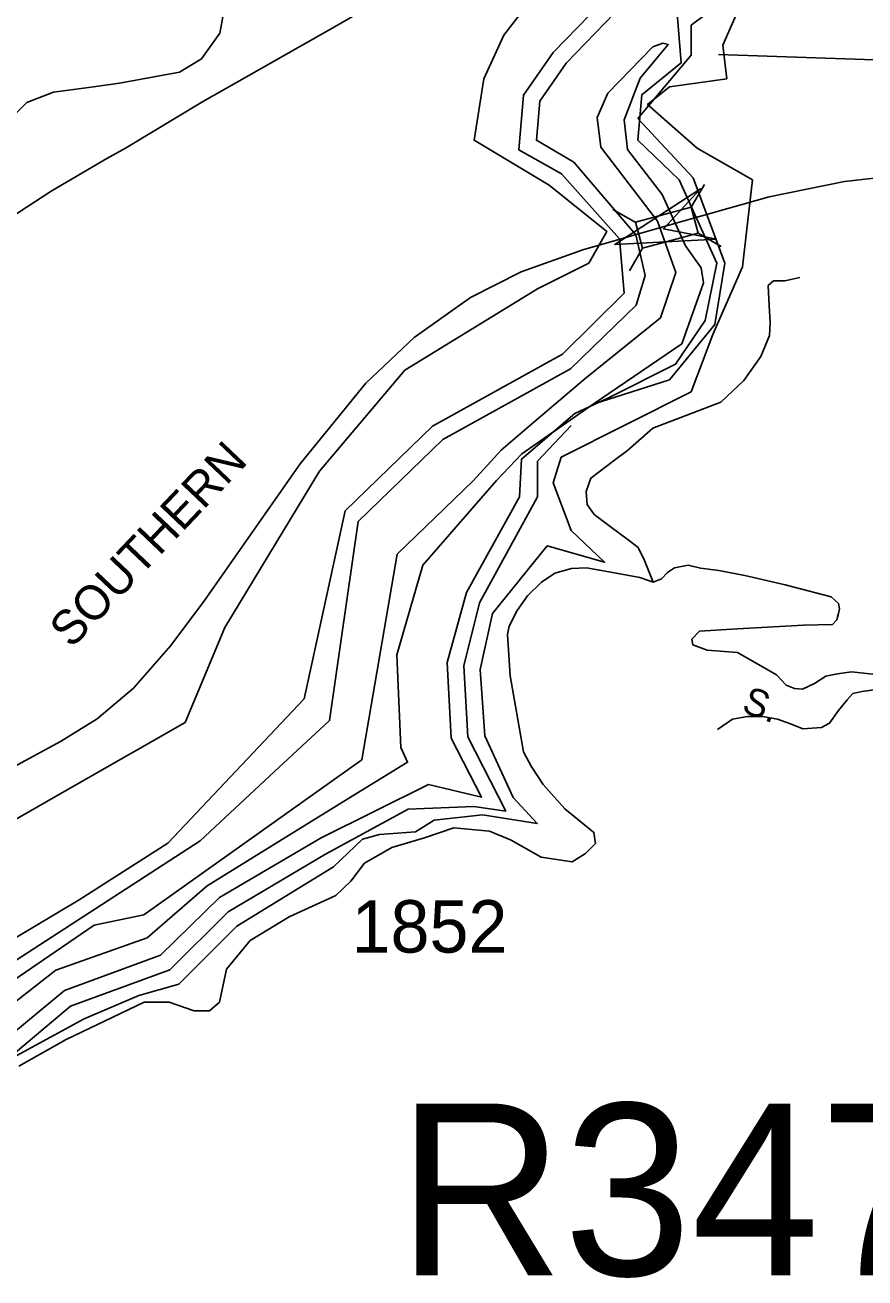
# Model space of a CAD drawing. Extents: x 884530 to 1028605, y 526725 to 653634.
# Drawn here: x 983469 to 985472, y 554302 to 557289 of the extents above; entities that cross this region are included whole.
import ezdxf

# ---------------------------------------------------------------- set-up
doc = ezdxf.new("R2010")
doc.units = 0
for name, color, linetype in [('Exist Hydrographic Bay Label', 7, 'Continuous'), ('Exist Hydrographic Buffer Line', 7, 'Continuous'), ('Exist Hydrographic Creek Single Shore', 7, 'Continuous'), ('Exist Railroad Mainline', 7, 'Continuous'), ('Exist Railroad Mainline Label', 7, 'Continuous'), ('Exist Road Non-System Type 51', 7, 'Continuous'), ('Exist Road Primary Interstate Structure Standard Bridge CELL', 7, 'Continuous'), ('Exist Road Primary US Structure RailRoad Number Label', 7, 'Continuous'), ('Exist Road Secondary Structure Standard Bridge Attributed CELL', 7, 'Continuous'), ('Exist Road Secondary Type 41 Attributed', 7, 'Continuous'), ('Exist Road Secondary Type 51 Attributed', 7, 'Continuous'), ('Exist Road Secondary Type 51 Label', 7, 'Continuous'), ('Exist Road Secondary Type 51 Number Label', 7, 'Continuous'), ('Exist Utilities Electrical Transmission Line', 7, 'Continuous')]:
    doc.layers.add(name, color=color, linetype=linetype)

msp = doc.modelspace()

# ---------------------------------------------------------------- linework, layer by layer
at = {"layer": 'Exist Hydrographic Bay Label'}
for points in [[(981773.4, 554673.1), (981811.5, 554652.9), (981929.6, 554719), (982322.3, 554872), (982708.3, 555125.6), (983123.8, 555210.7), (983586.4, 555475.2), (983850.8, 555626.4), (983945.2, 555853.1), (984171.7, 556225.9), (984374.7, 556466.8), (984691, 556660.5), (984813.8, 556721.9), (984856.3, 556797.5), (984719.3, 556907.6), (984539.9, 557014.8), (984563.5, 557161.2), (984610.8, 557265.2), (984738.2, 557430.5)], [(985185.3, 557359.6), (985133.4, 557241.5)], [(983449.1, 554832), (983610.4, 554920), (983740.7, 554975.4), (983836.2, 555002.3), (983974.4, 555140.6), (984205.1, 555282.6), (984273.5, 555347.8), (984314.2, 555359.2), (984400.6, 555365.7), (984444.6, 555393.4), (984560.3, 555406.5), (984690.6, 555385.3), (984633.6, 555447.2), (984565.4, 555594.7), (984554.3, 555752.5), (984583.8, 555886.4), (984714.6, 556047.9), (984851.5, 556008.6), (984771.3, 556084.2), (984728.8, 556197.6), (984747.7, 556259), (985057.9, 556414.9), (985109.8, 556551.9), (985180.6, 556712.5), (985204.2, 556920.3), (985072, 556995.9), (984954, 557099.8), (985005.9, 557142.3), (985142.8, 557161.2), (985133.4, 557241.5)]]:
    msp.add_lwpolyline(points, dxfattribs=at)
at = {"layer": 'Exist Hydrographic Buffer Line'}
for points in [[(981744.2, 554760.7), (981742.3, 554662.6), (981809, 554593.9), (981858, 554593.9), (981971.8, 554610.2), (982338.1, 554834.7), (982975.8, 554933.8), (983163, 554944.8), (983597.9, 555203.8), (983809.8, 555338.8), (984134.6, 555683.1), (984232.4, 556131), (984441.1, 556333.2), (984750.9, 556504.8), (984898, 556649.9), (984886.9, 556779.6), (984748.5, 556935), (984646.8, 556991.8), (984657.8, 557122), (984728.8, 557223.9), (984875.8, 557376), (984982.3, 557415.1), (985163.7, 557368.8), (985057.9, 557288.8)], [(981686.4, 554786.2), (981692.2, 554652.8), (981714.8, 554627.3), (981793.3, 554552.7), (981987.5, 554562.5), (982353.9, 554797.5), (983154.7, 554889.7), (983372.1, 555011), (983886.9, 555344.3), (984052, 555498.6), (984195.2, 555630.8), (984263.3, 556105.3), (984465.2, 556300.8), (984770.3, 556469.8), (984926.3, 556621.6), (984948.4, 556692), (984925.9, 556788.8), (984777.6, 556962.4), (984688.8, 557014.7), (984696.8, 557108), (984759.8, 557198.3), (984898.3, 557341.6), (984984.5, 557373.3), (985024.8, 557317.1)], [(985024.8, 557317.1), (985034.2, 557199), (984939.8, 557123.4), (984930.4, 557014.8), (985029.5, 556920.3), (985119.2, 556721.9), (985090.9, 556584.9), (985020.1, 556481), (984861, 556400.7), (984780.7, 556362.9), (984653.2, 556254.3), (984648.5, 556164.5), (984521.7, 555936.7), (984476.2, 555769.7), (984485.6, 555589.1), (984558.1, 555448.7), (984431.6, 555478.2), (984175.2, 555351.3), (983933.1, 555209.1), (983792, 555071.3), (983563.5, 554987.1), (983343.9, 554805.8)], [(985057.9, 557288.8), (985057.9, 557217.9), (984930.4, 557066.8)], [(984984.7, 556591.5), (985021.1, 556699.2), (984977.4, 556821.4), (984842.4, 556998.4), (984833.3, 557068.7), (984859.1, 557126.9), (984966, 557237.6), (984990.1, 557246.4), (985003.1, 557242.9), (984936.4, 557163.1), (984898.3, 557063.7), (984906.3, 556992.9), (984988.3, 556885.3), (985044, 556762.9), (985081.9, 556710.5), (985087, 556674.8), (985035.7, 556529.5)], [(984930.4, 557066.8), (985062.6, 556925), (985138.1, 556721.9), (985114.5, 556575.5), (985005.9, 556443.2), (984824.2, 556385.4)], [(984984.7, 556591.5), (984803.8, 556445.7), (984682.6, 556342.9), (984604.4, 556275.9)], [(984653.7, 556266.8), (984824.2, 556385.4), (985035.7, 556529.5)], [(984771.3, 556334.6), (984691, 556249.5), (984691, 556164.5), (984552.8, 555911.6), (984515.2, 555761.1), (984525.5, 555591.9), (984615.5, 555415.3), (984539.1, 555426), (984382.7, 555419.5), (984185.4, 555312.6), (983953.8, 555174.8), (983814.2, 555036.8), (983577.3, 554949.6), (983364.5, 554770.8), (983234, 554765.2), (983157.5, 554734.2), (983004.3, 554589.2), (982937.5, 554639.3)], [(984653.7, 556266.8), (984593.2, 556203.7), (984417.8, 556001.7), (984355.6, 555788.1), (984365.4, 555567), (984381.6, 555531.6), (984228.2, 555438), (983903.4, 555236.9), (983760.3, 555112.9), (983542.8, 555035.7), (983308.8, 554853.9), (983179.5, 554790.6), (983044, 554757.4), (983011.1, 554769), (982953, 554792.3)], [(983118.9, 554815.4), (983363.9, 554958.6), (983633.6, 555143.2), (983752, 555168), (984272.3, 555537.1), (984356.9, 556027.4), (984537.8, 556202.7), (984604.4, 556275.9)]]:
    msp.add_lwpolyline(points, dxfattribs=at)
at = {"layer": 'Exist Hydrographic Creek Single Shore'}
msp.add_lwpolyline([(985123.4, 557218.9), (985680.1, 557200), (985770.6, 557256.5), (985849, 557406.6), (985883.1, 557451), (986029.6, 557495.3), (986108, 557614.7), (986145.5, 557744.3), (986442.3, 557952.4), (986526.9, 558093.8), (986587.6, 558152.6), (986641.3, 558167.5), (986811.5, 558220.3), (986872.7, 558429.1), (986952.9, 558637), (987118.2, 559000.7), (987127.8, 559034.9), (987037.9, 559274.7), (987122.9, 559392.8), (987543.1, 559813.3), (987755.6, 559978.6)], dxfattribs=at)
at = {"layer": 'Exist Railroad Mainline'}
msp.add_lwpolyline([(983241.4, 555422.2), (983403.5, 555500.3), (983553.7, 555581.3), (983640.8, 555635.3), (983728, 555708.5), (983817, 555809.9), (983897, 555916.9), (984125.3, 556242.9), (984282.1, 556435.5), (984397.4, 556544.5), (984531.3, 556639.5), (984652, 556700.7), (984799.8, 556753.8), (985010.5, 556813.9), (985244, 556880.1), (985423.5, 556916.7), (985636.1, 556940.3)], dxfattribs=at)
at = {"layer": 'Exist Road Non-System Type 51'}
for points in [[(984967.1, 555961.3), (984946.3, 556012.3), (984931.3, 556043.6), (984907.3, 556061.6), (984864.9, 556093.4), (984826.6, 556122.3), (984809.8, 556146.3), (984807.3, 556177.5), (984818.2, 556208.7), (984874.6, 556251.9), (984905.9, 556274.8), (984966.5, 556328.3), (985128.6, 556390.3), (985183.3, 556441.7), (985223.6, 556499.2), (985244.3, 556549.5), (985246.1, 556580), (985243.6, 556619.8), (985241.5, 556668.7), (985254, 556679.5), (985281, 556679.5), (985317, 556687.2)], [(985880, 555819.2), (985826.2, 555798), (985796.9, 555781.7), (985780.6, 555767.1), (985746.4, 555749.1), (985689.3, 555734.5), (985632.3, 555734.5), (985599.7, 555726.3), (985546, 555711.7), (985464.5, 555700.2), (985443.3, 555695.4), (985430.3, 555680.7), (985409.1, 555654.6), (985387.9, 555624.5), (985368.4, 555614.7), (985324.4, 555611.4), (985295.1, 555622.8), (985264.1, 555634.2), (985228.3, 555640.8), (985192.4, 555640.8), (985156.6, 555634.2), (985120.7, 555609.8)]]:
    msp.add_lwpolyline(points, dxfattribs=at)
at = {"layer": 'Exist Road Primary Interstate Structure Standard Bridge CELL'}
for p, q in [((985089.3, 556909.4), (985058, 556855)), ((984925.6, 556818.3), (984871.3, 556849.6)), ((985129, 556761.7), (985074.6, 556793)), ((984941.9, 556757.7), (984910.5, 556703.4))]:
    msp.add_line(p, q, dxfattribs=at)
msp.add_lwpolyline([(985074.6, 556793), (984941.9, 556757.4), (984925.3, 556819.4), (985058, 556855)], close=True, dxfattribs=at)
at = {"layer": 'Exist Road Secondary Structure Standard Bridge Attributed CELL'}
msp.add_lwpolyline([(985119.2, 556778.6), (984875.7, 556766.3), (985080.4, 556898.7), (984991.7, 556803.7)], close=True, dxfattribs=at)
at = {"layer": 'Exist Road Secondary Type 41 Attributed'}
for points in [[(985326, 555858.7), (985395.3, 555860.4), (985405, 555871), (985409.1, 555886.4), (985411.6, 555897.8), (985409.1, 555910.1), (985392, 555926.4), (985282, 555954.9), (985185.9, 555976.5), (985124, 555988.7), (985080, 555994.4), (985050.7, 556001.4), (985018.1, 555994.8), (985001, 555984.2), (984987.1, 555968.8), (984967.1, 555961.3), (984935, 555972), (984874.7, 555983.4), (984838.9, 555989.5), (984807.9, 555995.2), (984772.1, 555993.6), (984732.9, 555982.7), (984701.2, 555961), (984667.8, 555928.4), (984642.5, 555893.4), (984623.8, 555855.9), (984619.9, 555836.4), (984626.2, 555737.3), (984646.5, 555620.3), (984658, 555556.8), (984675.9, 555522.6), (984704.5, 555478.6), (984756.2, 555420.8), (984825.9, 555364.3), (984829.3, 555337.7), (984806, 555314.4), (984773.7, 555294), (984700.4, 555305.4), (984628.7, 555346.2), (984576.7, 555367.6), (984491.8, 555375.5), (984421.8, 555351.1), (984343.6, 555328.3), (984278.4, 555290.8), (984245.8, 555248.4), (984210, 555214.2), (984098.9, 555162.7), (984005.9, 555106.2), (983949.3, 555038.2), (983933, 554959.9), (983908.6, 554938.7), (983872.7, 554938.7), (983813.1, 554959.9), (983753.3, 554959.9), (983567.3, 554870.2), (983454.3, 554807)], [(985491.4, 555741.4), (985440.1, 555747.1), (985406.7, 555742.2), (985379, 555736.5), (985352.1, 555719.4), (985323.6, 555706), (985304, 555707.6), (985284.5, 555715.7), (985261.2, 555740), (985168.2, 555793.2), (985096.3, 555799.2), (985062.1, 555811.5), (985059.6, 555825.3), (985077.6, 555844.1), (985168.2, 555849.7), (985326, 555858.7)]]:
    msp.add_lwpolyline(points, dxfattribs=at)
at = {"layer": 'Exist Road Secondary Type 51 Attributed'}
msp.add_lwpolyline([(982929.1, 556556.3), (982959.8, 556573.1), (983017.3, 556617.1), (983093.7, 556688.9), (983176.6, 556769.5), (983253, 556858), (983317.1, 556925), (983383.2, 557014.8), (983435.2, 557066.8), (983472.9, 557104.6), (983536.5, 557129.2), (983632.1, 557142.2), (983694, 557150.7), (983837.8, 557177.4), (983890, 557208.7), (983933.6, 557269.8), (983983.1, 557537.7)], dxfattribs=at)
at = {"layer": 'Exist Utilities Electrical Transmission Line'}
msp.add_lwpolyline([(984378.8, 557384.7), (984203.1, 557282.6), (983890.8, 557105.3), (983708.9, 556995.5), (983664, 556971), (983531.3, 556893.6), (983283.5, 556732)], dxfattribs=at)

# ---------------------------------------------------------------- texts
at = {"layer": 'Exist Railroad Mainline Label'}
msp.add_text('SOUTHERN', height=82.02, rotation=46.4932, dxfattribs=at).set_placement((983579.7, 555800.7))
at = {"layer": 'Exist Road Primary US Structure RailRoad Number Label'}
msp.add_text('R347', height=410.1, dxfattribs=at).set_placement((984357.4, 554307.8))
at = {"layer": 'Exist Road Secondary Type 51 Label'}
msp.add_text('S.', height=65.62, rotation=339.5985, dxfattribs=at).set_placement((985175.3, 555652.9))
at = {"layer": 'Exist Road Secondary Type 51 Number Label'}
msp.add_text('1852', height=125, dxfattribs=at).set_placement((984247.7, 555077.7))

doc.saveas('drawing.dxf')
